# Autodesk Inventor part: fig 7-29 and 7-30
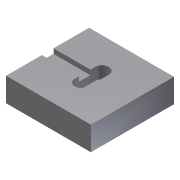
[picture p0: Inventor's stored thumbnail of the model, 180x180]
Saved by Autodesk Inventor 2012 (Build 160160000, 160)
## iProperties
Created: 2004-05
Part Number: fig 7-29 and 7-30
Document SubType Name: Modeling
Designer: CADCIM Technologies
Manufacturer: Standard
Standards Organization: Custom
Density: 1 g/cm^3
Material: Default
Author: CADCIM Technologies
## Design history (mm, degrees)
sketch "Sketch1"
  geometry: L1 (-30.233, -25.517)-(22.302, -25.517); L2 (22.302, -25.517)-(22.302, 25.904); L3 (22.302, 25.904)-(-30.233, 25.904); L4 (-30.233, 25.904)-(-30.233, -25.517)
  constraints: 8 end point, 2 parallel, 1 horizontal, 1 perpendicular
extrude "Extrusion1" new body sketch "Sketch1" distance "d0" = 14.75; taper "d1" = 0 deg
sketch "Sketch2"
  geometry: L1 (1.047, -5.75)-(1.047, 6.846); L2 (-7.35, 6.845)-(-7.35, -5.75); A1 r 4.198 centre (-3.152, 6.846) between (1.047, 6.846) and (-7.35, 6.845); A2 r 4.198 centre (-3.152, -5.75) between (-7.35, -5.75) and (1.047, -5.75)
  constraints: 4 end point, 4 point on circle, 4 tangent, 2 centre point, 1 parallel
extrude "Extrusion2" cut sketch "Sketch2" distance "d2" = 7.5; taper "d3" = 0 deg
sketch "Sketch3"
  geometry: L1 (-7.5, 0)-(-7.5, 12.595) reference; L2 (-7.5, 0)-(0, 0) reference; L3 (-7.5, 2.416)-(-4.537, 2.416); L4 (-4.537, 2.416)-(-4.537, 9.616); L5 (-4.537, 9.616)-(-7.5, 9.616)
  constraints: 6 end point, 2 perpendicular, 2 point on line, 1 parallel
extrude "Extrusion3" cut sketch "Sketch3" stored distance "d4" = 6.75; taper "d5" = 0 deg
body "Solid1"
